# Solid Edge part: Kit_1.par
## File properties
Sűrűség: 0,000 kg/m^3
Pontosság: 0,990
Author: bmolnar
Last saved by: ahadarics
Revision: 76
Username: bmolnar
Dokumentum tartalom típus: 0
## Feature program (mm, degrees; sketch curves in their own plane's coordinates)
base feature "unnamed BaseFeature 1"
sketch for "unnamed Hole 1" plane through (44.5, -44.5, -94.5) normal (0, 0, -1) x-axis (0, 1, 0)
  hole centre (0, 0) bore radius 4.188
hole "unnamed Hole 1" through
sketch for "unnamed Hole 2" plane through (44.5, -44.5, -94.5) normal (0, 0, -1) x-axis (0, 1, 0)
  hole centre (89, 0) bore radius 4.188
hole "unnamed Hole 2" through
sketch for "unnamed Hole 3" plane through (44.5, -44.5, -94.5) normal (0, 0, -1) x-axis (0, 1, 0)
  hole centre (0, -89) bore radius 4.188
hole "unnamed Hole 3" through
sketch for "unnamed Hole 4" plane through (44.5, -44.5, -94.5) normal (0, 0, -1) x-axis (0, 1, 0)
  hole centre (89, -89) bore radius 4.188
hole "unnamed Hole 4" through
pattern "unnamed Pattern 1" of "unnamed Hole 1", "unnamed Hole 2", "unnamed Hole 3", "unnamed Hole 4"
sketch for "Furat_5" plane through (56.5649, 0, -87.75) normal (0.999962, 0, -0.008727) x-axis (0, 1, 0)
  hole centre (-0.0002, 0.7496) bore radius 4.283
hole "Furat_5" diameter 8.566 finite
thread "unnamed Thread 1"
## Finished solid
Body 1: solid body, 320 faces, 800 edges, 501 vertices.
  Faces by surface: plane 145, cylinder 82, swept 56, cone 25, torus 11, spline 1
  Edges by curve: line 446, circle 180, spline 136, ellipse 28, curve on surface 10
Bounding box of the edges (mm; curved faces can reach further): 113.300 x 113.300 x 19.500, from (-56.65, -56.65, -97.5) to (56.65, 56.65, -78).
Cylindrical faces by radius (mm): R0.2 x48, R0.2006 x2, R0.2007 x2, R4.188 x4, R4.283 x1, R6.35 x4, R6.55 x4, R6.75 x4, R12.8 x1, R13.45 x1, R14 x1, R14.9 x1, R15 x1, R51.85 x8
Conical faces (half-angle, radius in mm at the cone's reference point): 0.5 deg R12.25 x4, 0.5 deg R35 x2, 3 deg R14.95 x1, 7 deg R14.2695 x1, 14 deg R12.65 x1, 14 deg R13.057 x1, 17 deg R12.65 x1, 23 deg R13.4211 x1, 42.5 deg R12.637 x1, 45 deg R4.185 x4, 45 deg R4.985 x4, 45 deg R13.6 x1, 84 deg R13.012 x1, 85 deg R14.6625 x1, 87 deg R12.7157 x1
Toroidal faces (ring radius, tube radius in mm): R6.05 r0.3 x2, R6.15 r0.2 x6, R13.4008 r0.225 x1, R13.8914 r0.325 x1, R14.7 r0.2 x1
Planar faces by outward normal: +x 16, +y 14, +z 2, -x 14, -y 16, -z 19, oblique 64
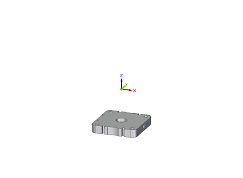
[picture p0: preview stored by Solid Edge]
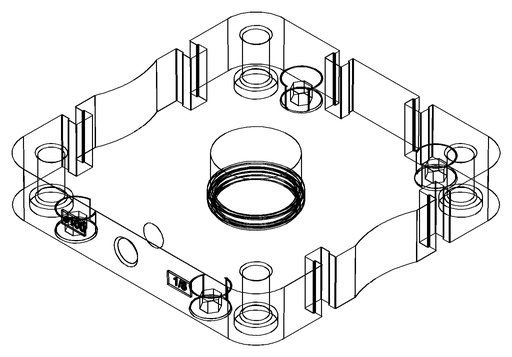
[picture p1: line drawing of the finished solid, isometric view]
